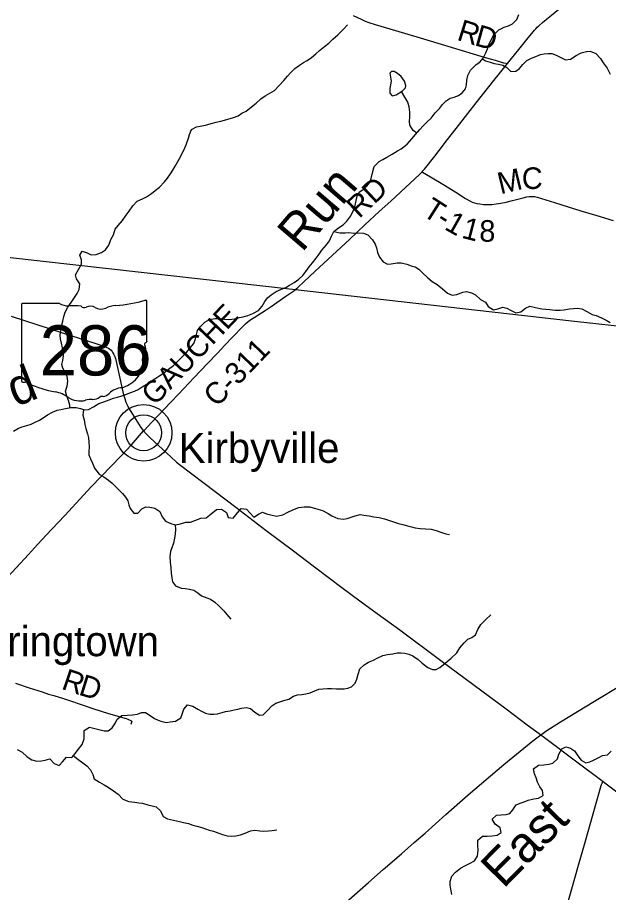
# Model space of a CAD drawing. Extents: x 1451455 to 1749751, y 218250 to 574981.
# Drawn here: x 1547700 to 1555909, y 407292 to 419441 of the extents above; entities that cross this region are included whole.
import ezdxf

# ---------------------------------------------------------------- set-up
doc = ezdxf.new("R2010")
doc.units = 0
for name, color, linetype in [('GM_X_County_Road', 7, 'Continuous'), ('GM_X_County_Road_Text', 7, 'Continuous'), ('GM_X_Minor_Lake', 7, 'Continuous'), ('GM_X_Minor_River', 7, 'Continuous'), ('GM_X_Minor_River_Text', 7, 'Continuous'), ('GM_X_State_Location', 7, 'Continuous'), ('GM_X_State_Route', 7, 'Continuous'), ('GM_X_State_Shield', 7, 'Continuous'), ('GM_X_Township', 7, 'Continuous'), ('GM_X_Township_Road', 7, 'Continuous'), ('GM_X_Township_Road_Text', 7, 'Continuous'), ('GM_X_Unincorporated', 7, 'Continuous'), ('GM_X_Unincorporated_Location', 7, 'Continuous'), ('GM_X_Unincorporated_Text', 7, 'Continuous')]:
    doc.layers.add(name, color=color, linetype=linetype)

msp = doc.modelspace()

# ---------------------------------------------------------------- linework, layer by layer
at = {"layer": 'GM_X_County_Road'}
for points in [[(1554504, 418801), (1554545, 418851), (1554662, 418996), (1554775, 419137), (1554861, 419244), (1554880, 419266), (1554898, 419286), (1554919, 419307), (1554940, 419327), (1554992, 419371), (1555220, 419555)], [(1552362, 419471), (1552471, 419418), (1552531, 419392), (1552580, 419373), (1552667, 419346), (1553076, 419223), (1553337, 419146), (1553877, 418981), (1554031, 418935), (1554196, 418887), (1554333, 418847), (1554450, 418813), (1554486, 418805), (1554504, 418801)], [(1553319, 417299), (1553330, 417311), (1553352, 417336), (1553496, 417518), (1553557, 417596), (1553674, 417746), (1553845, 417966), (1553956, 418108), (1554071, 418256), (1554316, 418568), (1554394, 418665), (1554468, 418757), (1554504, 418801)], [(1551563, 415666), (1551572, 415673), (1551592, 415692), (1551682, 415774), (1551830, 415913), (1552014, 416086), (1552309, 416361), (1552522, 416561), (1552725, 416747), (1552885, 416893), (1553089, 417083), (1553212, 417196), (1553288, 417268), (1553319, 417299)], [(1549452, 413700), (1549460, 413708), (1549568, 413822), (1549827, 414096), (1549942, 414217), (1550150, 414436), (1550340, 414635), (1550478, 414780), (1550581, 414890), (1550686, 415002), (1550828, 415152), (1550866, 415188), (1550903, 415220), (1550939, 415247), (1550986, 415277), (1551138, 415373), (1551223, 415430), (1551429, 415570), (1551496, 415617), (1551524, 415636), (1551550, 415655), (1551563, 415666)], [(1554967, 409481), (1555054, 409542), (1555241, 409662), (1555715, 409949), (1556099, 410178)], [(1552186, 407088), (1552574, 407430), (1552781, 407612), (1553034, 407831), (1553211, 407987), (1553361, 408116), (1553647, 408374), (1553960, 408649), (1554456, 409067), (1554856, 409398), (1554967, 409481)], [(1555299, 406988), (1555389, 407309), (1555494, 407672), (1555586, 407993), (1555696, 408383), (1555807, 408776), (1555813, 408792), (1555822, 408811), (1555836, 408833)]]:
    msp.add_lwpolyline(points, dxfattribs=at)
at = {"layer": 'GM_X_Minor_Lake'}
for points in [[(1553046, 418424), (1553089, 418465), (1553095, 418499), (1553074, 418557), (1553027, 418622), (1552978, 418663), (1552932, 418690), (1552896, 418691), (1552872, 418669), (1552888, 418559), (1552870, 418457), (1552871, 418391), (1552902, 418352), (1552959, 418367)], [(1552959, 418367), (1553046, 418424)]]:
    msp.add_lwpolyline(points, dxfattribs=at)
at = {"layer": 'GM_X_Minor_River'}
for points in [[(1552093, 416470), (1552158, 416519), (1552223, 416564), (1552273, 416615), (1552332, 416686), (1552368, 416764), (1552389, 416831), (1552406, 416901), (1552417, 416959), (1552446, 417015), (1552507, 417058), (1552558, 417103), (1552593, 417154), (1552612, 417206), (1552627, 417264), (1552654, 417371), (1552721, 417440), (1552772, 417471), (1552832, 417502), (1552905, 417545), (1552976, 417590), (1553027, 417617), (1553113, 417684), (1553178, 417755), (1553229, 417818), (1553289, 417887), (1553336, 417938), (1553389, 417991), (1553444, 418044), (1553502, 418119), (1553561, 418178), (1553604, 418232), (1553655, 418285), (1553710, 418320), (1553766, 418337), (1553825, 418356), (1553878, 418395), (1553923, 418452), (1553934, 418506), (1553943, 418570), (1553956, 418636), (1553992, 418709), (1554070, 418788), (1554122, 418823), (1554167, 418876), (1554205, 418950), (1554226, 419008), (1554247, 419061), (1554276, 419123), (1554318, 419200), (1554387, 419271), (1554460, 419306), (1554519, 419327), (1554577, 419352), (1554637, 419413), (1554662, 419484)], [(1548425, 414023), (1548427, 414060), (1548410, 414125), (1548383, 414185), (1548366, 414252), (1548389, 414321), (1548399, 414393), (1548388, 414458), (1548363, 414514), (1548330, 414571), (1548316, 414621), (1548328, 414677), (1548337, 414743), (1548336, 414799), (1548323, 414853), (1548310, 414919), (1548299, 414980), (1548294, 415032), (1548301, 415102), (1548317, 415174), (1548328, 415226), (1548345, 415291), (1548364, 415349), (1548397, 415419), (1548445, 415486), (1548482, 415539), (1548527, 415611), (1548556, 415666), (1548568, 415742), (1548521, 415811), (1548504, 415869), (1548547, 415943), (1548589, 416014), (1548588, 416078), (1548565, 416143), (1548598, 416196), (1548666, 416173), (1548721, 416144), (1548794, 416150), (1548865, 416179), (1548921, 416214), (1548967, 416280), (1548996, 416361), (1549032, 416425), (1549057, 416502), (1549100, 416554), (1549158, 416621), (1549211, 416696), (1549250, 416751), (1549300, 416826), (1549363, 416889), (1549436, 416922), (1549493, 416953), (1549562, 416998), (1549612, 417037), (1549674, 417086), (1549743, 417159), (1549782, 417210), (1549825, 417270), (1549856, 417321), (1549891, 417375), (1549929, 417442), (1549962, 417507), (1549991, 417567), (1550018, 417619), (1550046, 417686), (1550073, 417764), (1550090, 417816), (1550117, 417885), (1550184, 417924), (1550239, 417933), (1550309, 417948), (1550388, 417968), (1550460, 417989), (1550523, 418004), (1550577, 418015), (1550698, 418053), (1550763, 418078), (1550818, 418111), (1550878, 418142), (1550950, 418201), (1551013, 418254), (1551082, 418311), (1551141, 418352), (1551271, 418429), (1551336, 418498), (1551398, 418567), (1551451, 418626), (1551498, 418678), (1551553, 418735), (1551616, 418778), (1551671, 418815), (1551724, 418846), (1551785, 418887), (1551844, 418936), (1551895, 418985), (1551966, 419038), (1552025, 419085), (1552080, 419140), (1552151, 419201), (1552223, 419275)], [(1552223, 419275), (1552282, 419341)], [(1554159, 418866), (1554201, 418838), (1554267, 418821), (1554321, 418804), (1554381, 418791), (1554442, 418779), (1554496, 418746), (1554553, 418693), (1554622, 418698), (1554672, 418733), (1554719, 418787), (1554773, 418842), (1554841, 418878), (1554898, 418901), (1554965, 418926), (1555017, 418937), (1555071, 418940), (1555123, 418940), (1555181, 418918), (1555235, 418891), (1555312, 418854), (1555381, 418863), (1555458, 418912), (1555527, 418952), (1555603, 418969), (1555654, 418972), (1555733, 418943), (1555798, 418873), (1555833, 418811), (1555890, 418736), (1555931, 418653)], [(1553246, 417837), (1553194, 417872), (1553149, 417945), (1553146, 417995), (1553150, 418061), (1553149, 418128), (1553140, 418200), (1553123, 418266), (1553078, 418333), (1553034, 418416)], [(1547646, 413698), (1547713, 413737), (1547765, 413760), (1547830, 413777), (1547888, 413794), (1547947, 413821), (1548007, 413851), (1548058, 413881), (1548115, 413926), (1548184, 413962), (1548249, 413987), (1548303, 414000), (1548367, 414011), (1548442, 414026), (1548514, 414025), (1548576, 414010), (1548630, 413993), (1548686, 414000), (1548755, 414034), (1548830, 414081), (1548899, 414106), (1548973, 414131), (1549034, 414154), (1549090, 414171), (1549149, 414190), (1549205, 414207), (1549262, 414228), (1549325, 414253), (1549377, 414278), (1549432, 414311), (1549487, 414346), (1549556, 414391), (1549619, 414432), (1549676, 414471), (1549726, 414504), (1549798, 414557), (1549867, 414611), (1549926, 414668), (1549993, 414735), (1550045, 414788), (1550096, 414854), (1550149, 414917), (1550174, 414980), (1550186, 415040), (1550201, 415094), (1550236, 415146), (1550301, 415210), (1550368, 415247), (1550444, 415264), (1550503, 415263), (1550573, 415252), (1550637, 415249), (1550717, 415259), (1550780, 415274), (1550834, 415287), (1550899, 415302), (1550967, 415331), (1551046, 415373), (1551100, 415435), (1551133, 415498), (1551170, 415549), (1551221, 415589), (1551294, 415635), (1551365, 415668), (1551425, 415693), (1551480, 415724), (1551543, 415763), (1551606, 415810), (1551661, 415861), (1551706, 415914), (1551753, 415978), (1551797, 416033), (1551850, 416098), (1551889, 416153), (1551926, 416213), (1551994, 416284), (1552033, 416341), (1552062, 416405), (1552093, 416470)], [(1552093, 416470), (1552179, 416453), (1552252, 416453), (1552304, 416454), (1552370, 416449), (1552436, 416452), (1552506, 416447), (1552568, 416424), (1552631, 416355), (1552666, 416296), (1552687, 416243), (1552702, 416177), (1552727, 416115), (1552780, 416048), (1552839, 416016), (1552891, 416019), (1552972, 416034), (1553030, 416033), (1553106, 416016), (1553166, 415995), (1553222, 415980), (1553275, 415945), (1553326, 415896), (1553399, 415826), (1553461, 415777), (1553530, 415732), (1553603, 415672), (1553672, 415615), (1553738, 415586), (1553800, 415595), (1553885, 415627), (1553938, 415636), (1554005, 415619), (1554061, 415590), (1554132, 415527), (1554198, 415488), (1554239, 415429), (1554310, 415381), (1554370, 415398), (1554443, 415419), (1554495, 415406), (1554547, 415377), (1554622, 415340), (1554689, 415353), (1554756, 415406), (1554814, 415433), (1554896, 415413), (1554984, 415398), (1555036, 415393), (1555094, 415386), (1555170, 415378), (1555235, 415379), (1555289, 415382), (1555369, 415395), (1555424, 415402), (1555480, 415405), (1555540, 415398), (1555609, 415358), (1555681, 415317), (1555735, 415302), (1555812, 415271), (1555878, 415239), (1555934, 415206)], [(1548616, 413997), (1548608, 413919), (1548625, 413853), (1548636, 413792), (1548649, 413736), (1548674, 413659), (1548685, 413603), (1548690, 413543), (1548695, 413481), (1548692, 413417), (1548693, 413367), (1548714, 413312), (1548741, 413254), (1548770, 413185)], [(1548770, 413185), (1548832, 413101), (1548897, 413064), (1548962, 413017), (1549017, 412974), (1549086, 412907), (1549157, 412834), (1549202, 412783), (1549231, 412729), (1549248, 412676), (1549267, 412626), (1549318, 412559), (1549370, 412560), (1549429, 412618), (1549483, 412647), (1549537, 412644), (1549607, 412627), (1549676, 412582), (1549709, 412507), (1549756, 412448), (1549829, 412417), (1549891, 412398), (1549963, 412409), (1550039, 412434), (1550105, 412435), (1550165, 412456), (1550248, 412490), (1550319, 412493), (1550388, 412550), (1550465, 412611), (1550533, 412616), (1550602, 412567), (1550625, 412500), (1550695, 412491), (1550756, 412564), (1550807, 412625), (1550881, 412616), (1550930, 412561), (1550981, 412505), (1551047, 412544), (1551102, 412571), (1551159, 412552), (1551219, 412535), (1551295, 412518), (1551387, 412534), (1551455, 412571), (1551522, 412606), (1551606, 412637), (1551682, 412646), (1551758, 412646), (1551840, 412625), (1551935, 412595), (1552014, 412556), (1552066, 412523), (1552149, 412486), (1552227, 412477), (1552279, 412486), (1552335, 412503), (1552391, 412522), (1552459, 412539), (1552511, 412532), (1552583, 412521), (1552648, 412510), (1552722, 412497), (1552798, 412478), (1552865, 412458), (1552923, 412440), (1552990, 412416), (1553050, 412401), (1553116, 412382), (1553173, 412368), (1553225, 412355), (1553295, 412346), (1553367, 412342), (1553444, 412335), (1553514, 412316), (1553580, 412293), (1553649, 412272), (1553701, 412261)], [(1549891, 412398), (1549893, 412332), (1549888, 412274), (1549879, 412210), (1549866, 412144), (1549843, 412077), (1549824, 412025), (1549817, 411959), (1549820, 411877), (1549829, 411799), (1549836, 411727), (1549842, 411662), (1549855, 411606), (1549893, 411552), (1549972, 411516), (1550030, 411511), (1550087, 411502), (1550147, 411490), (1550205, 411455), (1550256, 411412), (1550329, 411385), (1550381, 411364), (1550442, 411323), (1550493, 411276), (1550564, 411201), (1550609, 411150), (1550664, 411089)], [(1548626, 409489), (1548625, 409543), (1548700, 409588), (1548757, 409573), (1548829, 409556), (1548903, 409536), (1548957, 409536), (1549013, 409579), (1549060, 409648), (1549085, 409700), (1549148, 409749), (1549224, 409755), (1549298, 409760), (1549366, 409767), (1549420, 409792), (1549476, 409793), (1549531, 409759), (1549601, 409707), (1549652, 409687), (1549706, 409666), (1549769, 409653), (1549819, 409660), (1549893, 409669), (1549968, 409718), (1549989, 409769), (1550012, 409839), (1550061, 409900), (1550135, 409881), (1550206, 409838), (1550257, 409809), (1550313, 409780), (1550370, 409769), (1550428, 409770), (1550480, 409775), (1550541, 409792), (1550591, 409804), (1550655, 409815), (1550707, 409826), (1550761, 409837), (1550813, 409850), (1550881, 409859), (1550935, 409848), (1550998, 409797), (1551061, 409752), (1551111, 409759), (1551176, 409822), (1551231, 409883), (1551290, 409920), (1551342, 409938), (1551400, 409959), (1551468, 409978), (1551535, 410019), (1551589, 410036), (1551649, 410041), (1551707, 410050), (1551765, 410065), (1551830, 410092), (1551886, 410115), (1551940, 410120), (1552004, 410125), (1552060, 410126), (1552130, 410121), (1552238, 410119), (1552288, 410129), (1552340, 410148), (1552391, 410199), (1552414, 410253), (1552431, 410322), (1552456, 410396), (1552515, 410455), (1552573, 410488), (1552644, 410519), (1552694, 410544), (1552772, 410581), (1552841, 410596), (1552911, 410607), (1552971, 410622), (1553023, 410621), (1553081, 410614), (1553134, 410601), (1553192, 410580), (1553267, 410527), (1553322, 410474), (1553397, 410415), (1553462, 410388), (1553514, 410389), (1553567, 410416), (1553642, 410477), (1553723, 410544), (1553800, 410619), (1553845, 410688), (1553902, 410757), (1553955, 410808), (1554009, 410831), (1554061, 410871), (1554093, 410944), (1554136, 411013), (1554205, 411082), (1554272, 411147)], [(1547694, 409278), (1547765, 409239), (1547834, 409177), (1547901, 409134), (1547967, 409117), (1548033, 409122), (1548083, 409131), (1548147, 409146), (1548210, 409083), (1548278, 409056), (1548324, 409108), (1548381, 409173), (1548453, 409167), (1548500, 409223), (1548549, 409282), (1548598, 409347), (1548625, 409425), (1548626, 409489)], [(1553734, 407264), (1553718, 407336), (1553709, 407393), (1553709, 407443), (1553733, 407520), (1553785, 407573), (1553852, 407630), (1553921, 407669), (1553977, 407696), (1554048, 407733), (1554091, 407797), (1554100, 407881), (1554095, 407945), (1554094, 408017), (1554159, 408072), (1554221, 408073), (1554295, 408078), (1554363, 408086), (1554416, 408126), (1554403, 408188), (1554334, 408243), (1554293, 408310), (1554354, 408365), (1554416, 408370), (1554488, 408377), (1554540, 408388), (1554581, 408439), (1554628, 408510), (1554682, 408534), (1554736, 408553), (1554794, 408572), (1554873, 408591), (1554937, 408602), (1555003, 408640), (1554994, 408709), (1554957, 408761), (1554922, 408824), (1554903, 408882), (1554880, 408939), (1554866, 409007), (1554938, 409060), (1555012, 409065), (1555082, 409073), (1555137, 409089), (1555199, 409148), (1555221, 409215), (1555260, 409287), (1555314, 409314), (1555382, 409295), (1555437, 409260), (1555482, 409191), (1555529, 409130), (1555594, 409093), (1555648, 409104), (1555700, 409128), (1555775, 409168), (1555827, 409192), (1555895, 409204), (1555946, 409254)], [(1548475, 409193), (1548537, 409144), (1548608, 409091), (1548665, 409052), (1548716, 408995), (1548745, 408929), (1548764, 408872), (1548837, 408823), (1548906, 408786), (1548960, 408753), (1549033, 408704), (1549100, 408659), (1549163, 408590), (1549248, 408556), (1549330, 408545), (1549384, 408538), (1549437, 408531), (1549509, 408510), (1549569, 408495), (1549626, 408482), (1549685, 408425), (1549724, 408347), (1549785, 408314), (1549867, 408298), (1549948, 408277), (1550004, 408262), (1550076, 408249), (1550133, 408228), (1550191, 408211), (1550259, 408194), (1550310, 408175), (1550364, 408156), (1550422, 408142), (1550497, 408114), (1550549, 408095), (1550614, 408078), (1550678, 408073), (1550732, 408081), (1550796, 408093), (1550862, 408116), (1550937, 408147), (1550995, 408158), (1551065, 408147), (1551119, 408142), (1551185, 408147), (1551239, 408152), (1551301, 408161)]]:
    msp.add_lwpolyline(points, dxfattribs=at)
at = {"layer": 'GM_X_State_Route'}
msp.add_lwpolyline([(1547614, 415292), (1548325, 415063), (1548801, 414912), (1548873, 414889), (1548915, 414873), (1548942, 414861), (1548964, 414848), (1548982, 414835), (1548999, 414820), (1549014, 414803), (1549026, 414785), (1549039, 414762), (1549050, 414735), (1549060, 414705), (1549070, 414667), (1549152, 414284), (1549172, 414200), (1549189, 414149), (1549205, 414102), (1549222, 414063), (1549243, 414022), (1549273, 413971), (1549414, 413749), (1549432, 413725), (1549451, 413702), (1549452, 413700), (1549488, 413660), (1549542, 413606), (1549830, 413341), (1549910, 413268), (1549950, 413234), (1550294, 412974), (1550734, 412641), (1551153, 412320), (1551534, 412038), (1551808, 411828), (1552053, 411643), (1552186, 411542), (1552474, 411330), (1552697, 411166), (1553010, 410939), (1553581, 410514), (1554045, 410171), (1554487, 409841), (1554781, 409621), (1554944, 409498), (1554967, 409481), (1555020, 409444), (1555469, 409106), (1555836, 408833), (1555877, 408801), (1556459, 408362)], dxfattribs=at)
at = {"layer": 'GM_X_State_Shield'}
for p, q in [((1547757, 415453), (1547757, 414396)), ((1548284, 415471), (1547774, 415471)), ((1549497, 414944), (1549497, 415497)), ((1549497, 414945), (1549497, 414944))]:
    msp.add_line(p, q, dxfattribs=at)
for centre, major_axis, start_param, end_param in [((1548877, 416911), (1845, 0), 4.814394, 5.042369), ((1549478, 415499), (19.4, 0), 6.141152, 7.989035), ((1547777, 415455), (20.2, 0), 1.712693, 3.28349), ((1548405, 415594), (196, 0), 4.042523, 4.731795), ((1548470, 414878), (702, 0), 1.404758, 1.657858), ((1548629, 415460), (56.4, 0), 3.836095, 5.185415), ((1548712, 415338), (117, 0), 0.950623, 2.079405), ((1548863, 415506), (141, 0), 4.081561, 5.145723), ((1549112, 415148), (371, 0), 1.699011, 2.107814), ((1549493, 414904), (30, 0), 1.883978, 3.671073), ((1549476, 414942), (20.7, 0), 5.05454, 6.418171), ((1549566, 414713), (131, 0), 2.387724, 3.262537), ((1549302, 414834), (180, 0), 5.934695, 6.695948), ((1548980, 414643), (462, 0), 5.101752, 6.440018), ((1547777, 414394), (20.3, 0), 3.00124, 4.508301), ((1547780, 414502), (155, 0), 4.665946, 4.897461), ((1547812, 414335), (56, 0), 0.519207, 1.627899), ((1548518, 415284), (1333, 0), 4.195997, 4.488961), ((1549175, 414099), (253, 0), 1.647645, 2.488434), ((1548121, 413921), (417, 0), 0.823519, 1.323587), ((1548744, 414251), (141, 0), 4.691044, 5.507374), ((1548872, 414148), (39.7, 0), 1.147584, 2.315152), ((1548855, 414294), (149, 0), 4.937069, 5.64225), ((1548572, 414330), (265, 0), 4.026481, 4.996735), ((1548725, 413965), (217, 0), 1.495662, 1.94098)]:
    msp.add_ellipse(centre, major_axis=major_axis, ratio=0.8, start_param=start_param, end_param=end_param, dxfattribs=at)
at = {"layer": 'GM_X_Township'}
for points in [[(1542043, 420309), (1541904, 419113), (1541888, 418982), (1541631, 416769), (1544045, 416508), (1548554, 416003), (1551520, 415667), (1555395, 415228), (1561908, 414519), (1562522, 414452), (1567474, 414060), (1573641, 413410), (1577383, 413049), (1580442, 412790), (1580491, 414838), (1580602, 418918), (1580746, 423359)], [(1538810, 393176), (1539083, 395731), (1539798, 401120), (1539880, 401684), (1540486, 406917), (1540842, 410533), (1540946, 411161), (1541060, 411851), (1541631, 416769), (1544045, 416508), (1548554, 416003), (1551520, 415667), (1555395, 415228), (1561908, 414519), (1562522, 414452), (1562129, 410880), (1562000, 409701), (1561586, 405939), (1561116, 401304), (1560611, 396564), (1560084, 391183)]]:
    msp.add_lwpolyline(points, dxfattribs=at)
at = {"layer": 'GM_X_Township_Road'}
for points in [[(1553319, 417299), (1553326, 417295), (1553436, 417230), (1553629, 417112), (1553788, 417014), (1553924, 416928), (1553981, 416895), (1554016, 416878), (1554047, 416867), (1554082, 416859), (1554121, 416852), (1554173, 416847), (1554229, 416846), (1554288, 416847), (1554347, 416853), (1554415, 416862), (1554489, 416877), (1554575, 416898), (1554724, 416939), (1554772, 416949), (1554808, 416954), (1554844, 416956), (1554882, 416955), (1554918, 416947), (1554978, 416930), (1555160, 416874), (1555523, 416759), (1555747, 416693), (1555975, 416622)], [(1546529, 410564), (1546545, 410587), (1546561, 410607), (1546582, 410633), (1546677, 410733), (1546878, 410949), (1547003, 411079), (1547341, 411441), (1547509, 411616), (1547851, 411984), (1547979, 412124), (1548102, 412256), (1548178, 412338), (1548356, 412527), (1548724, 412923), (1549141, 413354), (1549282, 413510), (1549452, 413700)], [(1547670, 410197), (1547863, 410133), (1548042, 410076), (1548132, 410047), (1548203, 410025), (1548338, 409984), (1548407, 409962), (1548624, 409888), (1548760, 409843), (1548963, 409779), (1549209, 409707), (1549232, 409699), (1549252, 409691), (1549273, 409682), (1549278, 409679), (1549284, 409673), (1549286, 409666), (1549283, 409654), (1549273, 409624)]]:
    msp.add_lwpolyline(points, dxfattribs=at)
at = {"layer": 'GM_X_Unincorporated'}
for radius in [393, 249]:
    msp.add_circle((1549452, 413675), radius, dxfattribs=at)
at = {"layer": 'GM_X_Unincorporated_Location'}
msp.add_line((1549452, 413675), (1549452, 413675), dxfattribs=at)

# ---------------------------------------------------------------- texts
at = {"layer": 'GM_X_County_Road_Text'}
for s, rotation, p in [('R', 342.6488, (1553790, 419134)), ('D', 344.3393, (1554035, 419058)), ('RD', 43.2648, (1552445, 416642)), ('GAUCHE', 46.5045, (1549608, 414039)), ('C-311', 46.1665, (1550470, 414019))]:
    msp.add_text(s, height=300, rotation=rotation, dxfattribs=at).set_placement(p)
at = {"layer": 'GM_X_Minor_River_Text'}
for s, height, rotation, p in [('Run', 500.1, 49.4497, (1551651, 416168)), ('Howard', 500, 21.3235, (1545871, 413328)), ('East', 500, 45.4652, (1554448, 407335))]:
    msp.add_text(s, height=height, rotation=rotation, dxfattribs=at).set_placement(p)
at = {"layer": 'GM_X_State_Location'}
msp.add_text('286', height=1, rotation=0, dxfattribs=at).set_placement((1548254, 414781))
for s in ['s', 'r']:
    msp.add_text(s, height=1, dxfattribs=at).set_placement((1548607, 414854))
at = {"layer": 'GM_X_State_Shield'}
msp.add_text('286', height=696.1, dxfattribs=at).set_placement((1548008, 414471))
at = {"layer": 'GM_X_Township_Road_Text'}
for s, rotation, p in [('M', 13.5409, (1554408, 416985)), ('C', 0.4293, (1554706, 417059)), ('T', 327.5378, (1553308, 416703)), ('-', 327.6483, (1553497, 416583)), ('1', 330.4821, (1553615, 416508)), ('1', 345.5319, (1553856, 416385)), ('8', 359.3918, (1554113, 416329)), ('R', 341.4058, (1548297, 410122)), ('D', 342.5488, (1548536, 410042))]:
    msp.add_text(s, height=300, rotation=rotation, dxfattribs=at).set_placement(p)
at = {"layer": 'GM_X_Unincorporated_Text'}
for s, p in [('Kirbyville', (1549940, 413257)), ('Stringtown', (1547031, 410573))]:
    msp.add_text(s, height=417, rotation=0, dxfattribs=at).set_placement(p)

doc.saveas('drawing.dxf')
